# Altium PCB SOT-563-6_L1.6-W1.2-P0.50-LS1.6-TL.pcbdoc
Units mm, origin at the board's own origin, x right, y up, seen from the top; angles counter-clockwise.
Board outline 15.02 x 14.45 mm, 2 copper layers (Top Layer, Bottom Layer), stack 0 mm thick; 1 components, 0 nets, 6 pads, 0 vias.
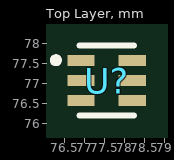
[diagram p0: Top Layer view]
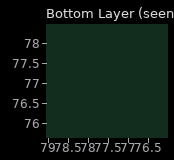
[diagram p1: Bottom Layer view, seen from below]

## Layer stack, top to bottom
Top Layer: signal copper (thickness not stored)
Bottom Layer: signal copper (thickness not stored)

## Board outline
84.875,69.85 69.85,69.85 69.85,84.302 84.875,84.302

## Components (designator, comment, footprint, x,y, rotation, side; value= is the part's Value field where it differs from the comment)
U? "" SOT-563-6_L1.6-W1.2-P0.50-LS1.6-TL 77.545,77.076 r0 top

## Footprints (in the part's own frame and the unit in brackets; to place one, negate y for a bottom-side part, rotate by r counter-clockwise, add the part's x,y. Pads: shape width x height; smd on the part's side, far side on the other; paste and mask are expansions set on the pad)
SOT-563-6_L1.6-W1.2-P0.50-LS1.6-TL [mm]
  rect 0.68x0.28 smd: 1(-0.64,0.5) 2(-0.64,0) 3(-0.64,-0.5) 4(0.64,-0.5) 5(0.64,0) 6(0.64,0.5)
  silkscreen extent -1.34,-0.88 0.68,0.88

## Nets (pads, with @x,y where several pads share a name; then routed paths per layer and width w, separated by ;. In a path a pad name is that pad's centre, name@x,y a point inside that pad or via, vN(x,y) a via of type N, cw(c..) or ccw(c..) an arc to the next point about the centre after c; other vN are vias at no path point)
pads on no net: U?.1 U?.2 U?.3 U?.4 U?.5 U?.6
